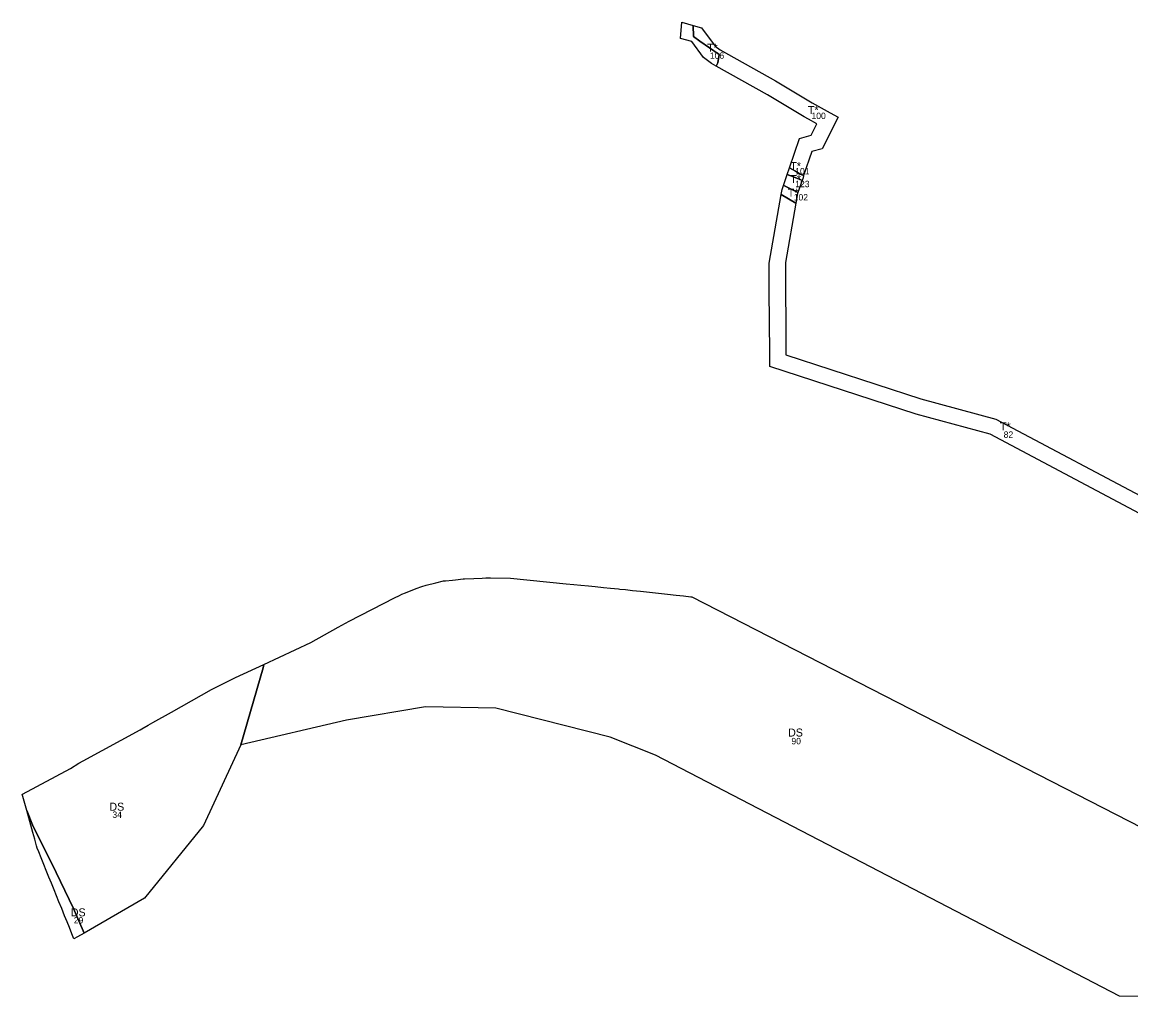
# Model space of a CAD drawing. Extents: x -521621 to -516990, y -1190025 to -1185905.
# Drawn here: x -521621 to -520236, y -1187659 to -1186440 of the extents above; entities that cross this region are included whole.
import ezdxf

# ---------------------------------------------------------------- set-up
doc = ezdxf.new("R2010")
doc.units = 0
doc.layers.add('fpl_id', color=7, linetype='Continuous')
doc.layers.add('v_infrastr_n', color=7, linetype='Continuous')

msp = doc.modelspace()

# ---------------------------------------------------------------- linework, layer by layer
at = {"layer": 'v_infrastr_n'}
for points in [[(-520797.2, -1186439.6), (-520783, -1186443.6), (-520782.5, -1186457.5), (-520774.7, -1186463.1), (-520750.6, -1186480.1), (-520752.2, -1186490.3), (-520754.3, -1186494.4), (-520760.1, -1186491.2), (-520770, -1186483.8), (-520784.7, -1186463.9), (-520799.1, -1186459.9)], [(-520749.2, -1186474.3), (-520680.3, -1186513), (-520634.4, -1186540.3), (-520611.9, -1186552.6), (-520601.9, -1186558), (-520621.9, -1186597.7), (-520634.9, -1186601.2), (-520645.1, -1186631.2), (-520649.5, -1186629.2), (-520655.4, -1186625.8), (-520662.9, -1186621.4), (-520650.4, -1186584.7), (-520635.7, -1186580.7), (-520628.5, -1186566.3), (-520638.9, -1186560.6), (-520644.3, -1186557.7), (-520690.3, -1186530.3), (-520754.3, -1186494.4), (-520752.2, -1186490.3), (-520750.6, -1186480.1), (-520774.7, -1186463.1), (-520782.5, -1186457.5), (-520783, -1186443.6), (-520772.7, -1186446.5), (-520755.7, -1186469.5)], [(-520665.7, -1186629.7), (-520662.9, -1186621.4), (-520655.4, -1186625.8), (-520652.7, -1186627.4), (-520649.5, -1186629.2), (-520645.1, -1186631.2), (-520645.9, -1186633.8), (-520647.1, -1186637.2), (-520651.4, -1186635.3), (-520654.8, -1186633.8), (-520657.7, -1186632.5)], [(-520665.7, -1186629.7), (-520657.7, -1186632.5), (-520654.8, -1186633.8), (-520651.4, -1186635.3), (-520647.1, -1186637.2), (-520652.2, -1186652.3), (-520669.1, -1186644.1), (-520670.4, -1186643.7)], [(-520670.4, -1186643.7), (-520669.1, -1186644.1), (-520652.2, -1186652.3), (-520652.7, -1186653.6), (-520654.8, -1186665.4), (-520673.2, -1186654.8), (-520672.1, -1186648.7)], [(-521348.2, -1187342), (-521394.8, -1187442.5), (-521468.2, -1187533.5), (-521543.9, -1187576.8), (-521556.9, -1187546.3), (-521578.8, -1187501.4), (-521608.2, -1187441.7), (-521615.5, -1187423.8), (-521621.2, -1187403.4), (-521620.8, -1187403.3), (-521561, -1187371.3), (-521550.3, -1187364.6), (-521545, -1187361.7), (-521473.9, -1187323), (-521471.9, -1187321.9), (-521463.9, -1187317.4), (-521457.9, -1187313.9), (-521434.7, -1187300.9), (-521384.9, -1187272.8), (-521354.9, -1187257.9), (-521319.4, -1187241.4), (-521320.1, -1187245.9)], [(-521578.8, -1187501.4), (-521556.9, -1187546.3), (-521543.9, -1187576.8), (-521552.2, -1187581.5), (-521556.6, -1187584), (-521559.1, -1187577.9), (-521562.2, -1187570.1), (-521565.1, -1187562.9), (-521568.2, -1187555.4), (-521571.8, -1187546.4), (-521575.2, -1187538), (-521581.4, -1187522.7), (-521584.6, -1187514.7), (-521587.8, -1187507), (-521591.1, -1187498.8), (-521594.2, -1187491.1), (-521597.5, -1187483), (-521600.5, -1187475.6), (-521602.4, -1187470.8), (-521603.2, -1187467.9), (-521605.5, -1187459.8), (-521607.9, -1187451.3), (-521615.5, -1187423.8), (-521608.2, -1187441.7)]]:
    msp.add_lwpolyline(points, close=True, dxfattribs=at)
for points in [[(-520212.4, -1187059.9), (-520412.3, -1186953.8), (-520504.6, -1186929.1), (-520687.3, -1186869.5), (-520687.4, -1186853.1), (-520687.5, -1186835.5), (-520687.6, -1186830.6), (-520687.6, -1186824.5), (-520687.8, -1186807), (-520688, -1186781.6), (-520688.2, -1186740.5), (-520673.2, -1186654.8), (-520654.8, -1186665.4), (-520667.8, -1186739.5), (-520667.4, -1186850.6), (-520667.4, -1186855), (-520498.9, -1186909.9), (-520405, -1186935.1), (-520203.8, -1187041.8)], [(-519963.3, -1187659), (-520250.8, -1187655.6), (-520830.3, -1187354.9), (-520886.9, -1187332.1), (-521029.4, -1187296.2), (-521117.3, -1187294.5), (-521216.3, -1187310.9), (-521348.2, -1187342), (-521320.1, -1187245.9), (-521319.4, -1187241.4), (-521260.5, -1187213.9), (-521226.5, -1187195.1), (-521212.6, -1187187.3), (-521169.7, -1187165.3), (-521156, -1187158.2), (-521150.1, -1187155.2), (-521146.9, -1187153.6), (-521142.4, -1187151.9), (-521129.1, -1187146.8), (-521121.8, -1187144.1), (-521116.4, -1187142.7), (-521104.7, -1187139.7), (-521094.9, -1187137.3), (-521092.5, -1187137), (-521083.9, -1187136.1), (-521079.9, -1187135.7), (-521070.4, -1187134.7), (-521068.7, -1187134.7), (-521057.1, -1187134.1), (-521046.7, -1187133.6), (-521042.2, -1187133.4), (-521036.4, -1187133.4), (-521011.3, -1187133.7), (-520941.8, -1187140.7), (-520932.3, -1187141.6), (-520923.4, -1187142.5), (-520914, -1187143.4), (-520905.5, -1187144.3), (-520895.3, -1187145.3), (-520886.2, -1187146.2), (-520876.4, -1187147.2), (-520874.6, -1187147.4), (-520867.8, -1187148.1), (-520858.8, -1187149.1), (-520849, -1187150.2), (-520815.2, -1187153.9), (-520804.3, -1187155.1), (-520795.3, -1187156), (-520786.2, -1187157), (-520784.9, -1187157.2), (-520159, -1187477.9)]]:
    msp.add_lwpolyline(points, dxfattribs=at)

# ---------------------------------------------------------------- texts
at = {"layer": 'fpl_id'}
for s, p in [('106', (-520762.2, -1186485.3)), ('100', (-520635.3, -1186560.5)), ('101', (-520655.6, -1186629.6)), ('123', (-520655.6, -1186645.6)), ('102', (-520657.5, -1186662.2)), ('82', (-520395.3, -1186958.6)), ('90', (-520660.4, -1187341.2)), ('34', (-521508.5, -1187433.1)), ('29', (-521556.7, -1187564.9))]:
    msp.add_text(s, height=8, dxfattribs=at).set_placement(p)
at = {"layer": 'v_infrastr_n'}
for s, p in [('T*', (-520765.7, -1186476.6)), ('T*', (-520639.8, -1186554.4)), ('T*', (-520661.8, -1186624.3)), ('T*', (-520661.8, -1186640.4)), ('T*', (-520665, -1186657.4)), ('T*', (-520400, -1186949.2)), ('DS', (-520664.6, -1187331.5)), ('DS', (-521512.3, -1187424.1)), ('DS', (-521560.5, -1187556))]:
    msp.add_text(s, height=10, dxfattribs=at).set_placement(p)

doc.saveas('drawing.dxf')
